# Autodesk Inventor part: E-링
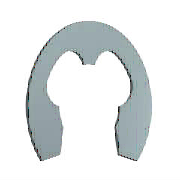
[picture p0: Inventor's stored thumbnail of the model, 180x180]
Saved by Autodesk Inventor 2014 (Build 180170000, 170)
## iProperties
IsCustomPart: 1
Created: 2012-02
Part Number: E-링
Material: 강철, 연강
Description: 일반용 테이퍼 및 줄어든 횡단면 리테이닝 링 - E-링 외부 시리즈 3CM1 리테이닝 링
Document SubType Name: Modeling
Standard: ANSI B27.7
Designer: mduedu
Standard Revision: 1999
Standards Organization: ANSI
Language: ko-KR
Size Designation: 5
Categories: <MemberInstance><Categories><Category DisplayName="샤프트 부품" InternalName="7f7aeb1f-a693-4053-b835-cee3144e0d98" Mnemonic="SHFT"><Category DisplayName="써클립" Inter
Density: 7.86 g/cm^3
Mass: 0.124025 g
Surface Area: 0.760929 cm^2
Volume: 0.0157793 cm^3
Appearance: 파란색 - 벽 페인트 - 광택
Author: mduedu
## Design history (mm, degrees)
sketch "스케치1"
  geometry: L1 (-0.39, 0.024)-(0, 0.024) reference; L2 (-3.206, 0)-(3.486, 0) reference; L3 (-1.787, -3.256)-(1.787, -3.256); L4 (0, 1.949)-(0, -3.479) reference; L5 (-2.34, -1.696)-(-1.958, -1.696); L6 (-0.39, -0.136)-(-0.39, 0.242); L7 (0, 1.774)-(2.53, 1.774); L8 (-1.787, -3.256)-(-2.367, -4.889); L9 (0, -0.526)-(-1.278, -0.526); L10 (1.787, -3.256)-(2.367, -4.889); L11 (2.34, -1.696)-(1.958, -1.696); L12 (0.39, -0.136)-(0.39, 0.242); C1 r 2.5 at (0, -2.476); A1 r 1.95 centre (0, -2.476) between (-1.847, -1.851) and (-1.787, -3.256); A2 r 0.39 centre (0, -0.136) between (-0.39, -0.136) and (0.39, -0.136); A3 r 4.25 centre (0, -2.476) between (3.384, -5.047) and (-3.384, -5.047); A4 r 3.12 centre (0, -2.476) between (-0.78, 0.545) and (-2.753, -1.008); A5 r 0.312 centre (-0.702, 0.242) between (-0.39, 0.242) and (-0.78, 0.545); A6 r 0.468 centre (-2.34, -1.228) between (-2.753, -1.008) and (-2.34, -1.696); A7 r 0.117 centre (-1.958, -1.813) between (-1.847, -1.851) and (-1.958, -1.696); A8 r 0.585 centre (-2.919, -4.693) between (-3.384, -5.047) and (-2.367, -4.889); A9 r 0.585 centre (2.919, -4.693) between (2.367, -4.889) and (3.384, -5.047); A10 r 1.95 centre (0, -2.476) between (1.787, -3.256) and (1.847, -1.851); A11 r 0.117 centre (1.958, -1.813) between (1.958, -1.696) and (1.847, -1.851); A12 r 0.468 centre (2.34, -1.228) between (2.34, -1.696) and (2.753, -1.008); A13 r 3.12 centre (0, -2.476) between (2.753, -1.008) and (0.78, 0.545); A14 r 0.312 centre (0.702, 0.242) between (0.78, 0.545) and (0.39, 0.242); 1 further point
  constraints: 30 point on circle, 20 end point, 15 centre point, 13 symmetric about line, 12 tangent, 8 point on line, 4 parallel, 2 coincident, 2 horizontal, 1 concentric, 1 perpendicular, 1 vertical alignment, 9 other
  dimensions: "d0" = 5 diameter of C1 (= WD); "d3" = 0.78 distance from line of A1.centre L3 (= 0.2 x ND); "d4" = 0.39 radius of A2 (= 0.1 x ND); "d5" = 8.5 diameter of A3 (= SD2); "d8" = 3.12 radius of A4 (= 0.8 x ND); "d9" = 0.78 distance from line of A1.centre L5 (= 0.2 x ND); "d10" = 0.312 radius of A5 (= 0.08 x ND); "d11" = 0.468 radius of A6 (= 0.12 x ND); "d12" = 0.117 radius of A7 (= 0.03 x ND); "d13" = 0.585 radius of A8 (= 0.15 x ND); "d14" = 1.95 distance from line of A1.centre L9 (= 0.5 x ND); "d15" = 1.95 radius of A1 (= 0.5 x ND)
extrude "본체" new body sketch "스케치1" distance "d16" = 0.6 (= SD); taper "d17" = 0 deg
workaxis "Work Axis1"
workaxis "Work Axis2"
workplane "Work Plane1"
body "Solid1"
other parameters: "ND" = 3.9 [user parameter; used in 14 equation terms], "SD" = 0.6 [user parameter; used in 1 equation term], "WD" = 5 (= WDMIN) [user parameter; used in 1 equation term], "d1" = 6.24 (= 1.6 x ND), "d2" = 3.9 (= ND), "SD2" = 8.5 [user parameter; used in 1 equation term], "d6" = 3.9 (= ND), "d7" = 0.585 (= 0.15 x ND), "d18" = 0, "d19" = 0, "d27" = 0, "d28" = 0, "WDMIN" = 5 [user parameter; used in 1 equation term], "SNB" = 0.7 [user parameter], "WDMAX" = 6 [user parameter], "BUBRMI" = 1.1 [user parameter]
